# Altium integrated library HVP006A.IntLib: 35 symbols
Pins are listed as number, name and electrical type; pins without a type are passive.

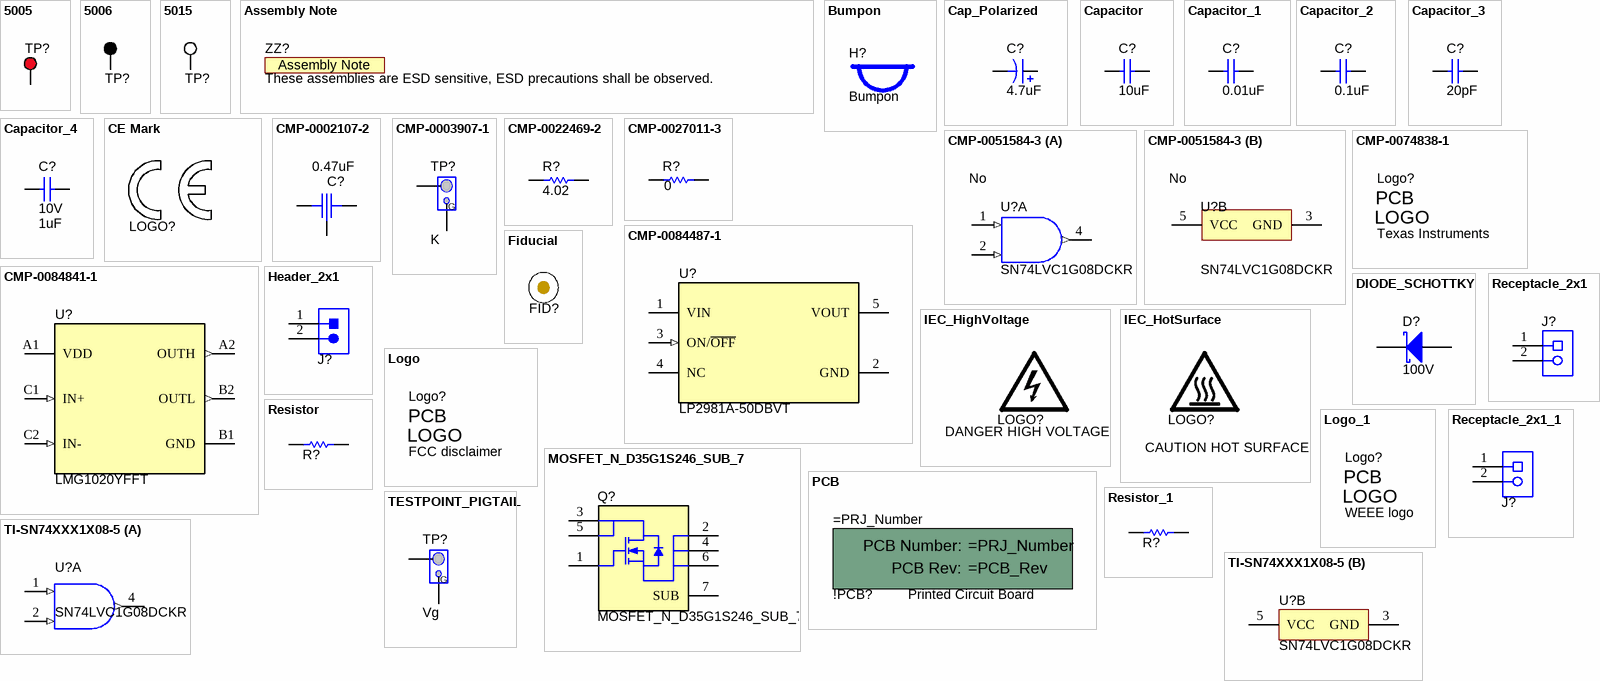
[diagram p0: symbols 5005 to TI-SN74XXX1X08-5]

## 5005
designator TP?  (value not drawn)
Test Point, Compact, Red, TH; Manufacturer: Keystone; CNHeader: FALSE; ContactFinish: Silver; CT: TRUE; Green_Lifecycle: Active; Green_REACh: Passed
footprint Keystone5005 (Keystone Compact loops)
pins: 1

## 5006
designator TP?  (value not drawn)
Test Point, Compact, Black, TH; Manufacturer: Keystone; CNHeader: FALSE; ContactFinish: Silver; CT: TRUE; Green_Lifecycle: Active; Green_REACh: Passed
footprint Keystone5006 (Keystone Compact loops)
pins: 1

## 5015
designator TP?  (value not drawn)
Test Point, Miniature, SMT; Manufacturer: Keystone; CNHeader: FALSE; CT: TRUE; Green_Lifecycle: Active; Green_REACh: Passed
footprint Testpoint_Keystone_Miniature (Miniature SMT test point)
pins: 1

## Assembly Note
designator ZZ?, comment These assemblies are ESD sensitive, ESD precautions shall be observed.  (no BOM)
CompType: AssemblyNote
footprint AssemblyNote (Assembly Note)

## Bumpon
designator H?
Bumpon, Hemisphere, 0.44 X 0.20, Clear; Manufacturer: 3M; PartNumber: SJ-5303 (CLEAR)
footprint Bumpon_SJ5003Transparent (3M Hemispherical Bumpon transparent)

## Cap_Polarized
designator C?  value 4.7uF  (hidden comment: Cap_Polarized)
CAP, AL, 4.7 uF, 100 V, +/- 20%, SMD; PartNumber: UUX2A4R7MCL1GS; Manufacturer: Nichicon; Polarized: Y; CompType: Capacitor; U/M: EA; Cap_F: 4.7µF; Value1: Unknown; VDC_V: 100V; IRMS_A: 42mA; TaMin_C: -55°C; TaMax_C: 105°C; Cap_Case: 8x6.2mm; SizeAreaWB_mm2: 106.09; SizeArea_mm2: 68.89; SizeX_mm: 8.3; SizeZ_mm: 6.5; AEC Category: Q200; AEC Qualified: N
footprint UUX_800x620 (SMD, 2-Leads, Dia 8mm)
pins: 1 +, 2 -

## Capacitor
designator C?  ValueDisplayed: 10uF  (hidden comment: Capacitor)
CAP, CERM, 10 uF, 25 V, +/- 10%, X7R, 1206; PartNumber: 885012208069; Manufacturer: Wurth Elektronik; Polarized: N; Value: 10uF; U/M: EA; Cap_F: 10µF; Value1: Unknown; VDC_V: 25V; TaMin_C: -55°C; TaMax_C: 125°C; Cap_Case: 1206; AEC Category: Q200; SizeArea_mm2: 5.12; SizeAreaWB_mm2: 10.92; SizeX_mm: 3.2; SizeY_mm: 1.6; SizeZ_mm: 1.35
footprint 1206 (1206 from SM-752 data)
footprint 1206L (1206 from SM-752 data)
footprint 1206M (1206 from SM-752 data)
pins: 1, 2

## Capacitor_1
designator C?, comment ValueDisplayed: 0.01uF  (hidden comment: Capacitor)
CAP, CERM, 0.01 uF, 100 V, +/- 1%, C0G/NP0, 0805; PartNumber: C0805C103F1GACTU; Manufacturer: Kemet; Polarized: N; Value: 0.01uF; U/M: EA; Cap_F: 10nF; Value1: Unknown; VDC_V: 100V; TaMin_C: -55°C; TaMax_C: 125°C; Cap_Case: 0805; SizeArea_mm2: 2.5; SizeAreaWB_mm2: 6.75; SizeX_mm: 2; SizeY_mm: 1.25; SizeZ_mm: 1.45; AEC Category: Q200
footprint 0805_HV (0805 with 30mil clearance between pads)
footprint 0805M (0805 from SM-752 data)
footprint 0805 (0805 from SM-752 data)
footprint 0805L (0805 from SM-752 data)
footprint 0805_HV1 (Custom footprint based on analyzing multiple manufacturer recommendations)
pins: 1, 2

## Capacitor_2
designator C?, comment ValueDisplayed: 0.1uF  (hidden comment: Capacitor)
CAP, CERM, 0.1 uF, 25 V, +/- 10%, X7R, 0603; PartNumber: GRM188R71E104KA01D; Manufacturer: MuRata; Polarized: N; Value: 0.1uF; U/M: EA; Cap_F: 100nF; Value1: Unknown; VDC_V: 25V; TaMin_C: -55°C; TaMax_C: 125°C; Cap_Case: 0603; AEC Category: Q200; SizeArea_mm2: 1.28; SizeAreaWB_mm2: 4.68; SizeX_mm: 1.6; SizeY_mm: 0.8; SizeZ_mm: 1
footprint 0603 (0603 from SM-752 data)
footprint 0603_HV (Ernesto recommended land pattern.  26 mil between pads.)
footprint 0603L (0603 from SM-752 data)
footprint 0603S
footprint 0603M (0603 from SM-752 data)
pins: 1, 2

## Capacitor_3
designator C?, comment ValueDisplayed: 20pF  (hidden comment: Capacitor)
CAP, CERM, 20 pF, 50 V, +/- 5%, C0G/NP0, 0402; PartNumber: GRM1555C1H200JA01D; Manufacturer: MuRata; Polarized: N; Value: 20pF; U/M: EA; Value1: Unknown; VDC_V: 50V; TaMin_C: -55°C; TaMax_C: 125°C; Cap_Case: 0402; SizeArea_mm2: 0.5; SizeAreaWB_mm2: 3; SizeX_mm: 1; SizeZ_mm: 0.6; AEC Category: Q200
footprint 0402 (0402 from SM-752 data)
footprint 0402S (Based on C0402S footprint from PADS legacy)
footprint 0402L (0402 from SM-752 data)
footprint 0402M (0402 from SM-752 data)
pins: 1, 2

## Capacitor_4
designator C?, comment VDC_V: 10V  ValueDisplayed: 1uF  (hidden comment: LWK107BJ105MV)
CAP, CERM, 1 uF, 10 V, +/- 20%, X5R, 0306; Manufacturer: Taiyo Yuden; TaMin_C: -55°C; Polarized: N; SizeAreaWB_mm2: 4.68; Value1: Unknown; U/M: EA; Value: 1uF; TaMax_C: 85°C; SizeZ_mm: 0.6; SizeX_mm: 0.8; SizeY_mm: 1.6; Cap_Case: 0306; SizeArea_mm2: 1.28; CompType: Capacitor; Cap_F: 1µF; AEC Category: Q200
footprint 0306 (based on TDK recommendation (similar to Taiyo Yuden and MuRata))
pins: 1, 2

## CE Mark
designator LOGO?  (value not drawn)  (no BOM)
SymbolCreator: a0412235
footprint CE_Mark_5mm (Minimum text height for CE Mark)
footprint CE_Mark_10mm (Double the minimum text height for CE Mark)

## CMP-0002107-2
designator C?, comment value 0.47uF  (hidden comment: Capacitor_Balanced)
Feedthru Capacitor, 0.47uF, 6.3V, SMD; PartNumber: YFF18PW0J474M; Manufacturer: TDK; CompType: Filter
footprint YFF18PW (TDK)
pins: 1, 2, 3

## CMP-0003907-1
designator TP?, comment K  (no BOM)
PIGTAIL; Manufacturer: Texas Instruments; Key: TESTPOINT_PIGTAIL; CompType: Test Point
footprint TESTPOINT_PIGTAIL (Pigtail)
pins: 1, 2

## CMP-0022469-2
designator R?, comment ValueDisplayed: 4.02  (hidden comment: CRCW06034R02FKEA)
RES, 4.02, 1%, 0.1 W, 0603; Manufacturer: Vishay-Dale; Power_W: 100mW; TempCo: 100 ppm/C; Value_Code: 4R02; U/M: EA; Value: 4.02; EIA_Code: E96; SizeX_mm: 1.6; SizeY_mm: 0.8; SizeZ_mm: 1; Value2: 0.1W; SizeArea_mm2: 1.28; CompType: Resistor; VDC_V: 75V; AEC Category: Q200
footprint 0603 (0603 from SM-752 data)
footprint 0603_HV (Ernesto recommended land pattern.  26 mil between pads.)
footprint 0603L (0603 from SM-752 data)
footprint 0603S
footprint 0603M (0603 from SM-752 data)
pins: 1, 2

## CMP-0027011-3
designator R?, comment ValueDisplayed: 0  (hidden comment: ERJ-1GE0R00C)
RES, 0, 5%, 0.05 W, 0201; Manufacturer: Panasonic; Power_W: 50mW; TempCo: 600 ppm/C; Value_Code: 0000; U/M: EA; Value: 0; EIA_Code: E24; SizeX_mm: 0.6; SizeY_mm: 0.3; SizeZ_mm: 0.26; Value2: 0.05W; SizeArea_mm2: 0.18; CompType: Resistor; VDC_V: 15V; AEC Category: Q200
footprint 0201 (Data from Kemet datasheet CC101_COM dated 7/28/11)
footprint 0201_Silk (Data from Kemet datasheet CC101_COM dated 7/28/11)
footprint 0201L (Data from Kemet datasheet CC101_COM dated 7/28/11)
footprint 0201M (Data from Kemet datasheet CC101_COM dated 7/28/11)
pins: 1, 2

## CMP-0051584-3
designator U?, comment 3-State Output: No  (hidden comment: SN74LVC1G08DCKR)
Single 2-Input Positive-AND Gate, DCK0005A, LARGE T&R; Manufacturer: Texas Instruments; tpd @ Nom Voltage(Max)(ns): 4.5,6,4,5; F @ Nom Voltage(Max)(Mhz): 150; ICC @ Nom Voltage(Max)(mA): 0.01; Bits(#): 1; VCC(Min)(V): 1.65; Gate Type: AND; Rating: Catalog; Output Type: CMOS; Voltage(Nom)(V): 1.8,2.5,3.3,5; Technology Family: LVC; VCC(Max)(V): 5.5; Input Type: CMOS/TTL; Output Drive (IOL/IOH)(Max)(mA): 32/-32; Logic: True; AEC Category: Q200; AEC Qualified: N; CompType: IC; SizeAreaWB_mm2: 9.3; SizeArea_mm2: 4.2; SizeX_mm: 2.1; SizeY_mm: 2.0; SizeZ_mm: 1.1
footprint DCK0005A_N (SOT353, 5-Leads, Body 2x1.3mm, Pitch 0.65mm, Lead Span 2.1mm, IPC Medium Density)
footprint DCK0005A_M (SOT353, 5-Leads, Body 2x1.3mm, Pitch 0.65mm, Lead Span 2.1mm, IPC Low Density)
footprint DCK0005A_L (SOT353, 5-Leads, Body 2x1.3mm, Pitch 0.65mm, Lead Span 2.1mm, IPC High Density)
part A pins: 1 A (in) "Input A", 2 B (in) "Input B", 4 Y (out) "Output Y"
part B pins: 3 GND (power) "Ground Pin", 5 VCC (power) "Power Pin"

## CMP-0074838-1
designator Logo?, comment Texas Instruments  (no BOM)
Texas Instrument Corporate Signature; SymbolCreator: a0412235; Library Reference: Logo; Lib Reference: TI_Logo
footprint TI_Horizontal_Overlay_Medium
footprint TI_Horizontal_Overlay_Small
footprint TI_Stacked_SolderMask_Small
footprint TI_Stacked_SolderMask_Small_Vertical
footprint TI_Symbol_Overlay_Medium
footprint TI_Symbol_Overlay_Small
footprint TI_Symbol_SolderMask_Medium
footprint TI_Symbol_SolderMask_Small
footprint TI_Horizontal_SolderMask_Medium
footprint TI_Horizontal_SolderMask_Small
footprint TI_Stacked_Overlay_Medium
footprint TI_Stacked_Overlay_Medium_Vertical
footprint TI_Stacked_Overlay_Small
footprint TI_Stacked_Overlay_Small_Vertical
footprint TI_Stacked_SolderMask_Medium
footprint TI_Stacked_SolderMask_Medium_Vertical

## CMP-0084487-1
designator U?, comment LP2981A-50DBVT
100-mA Ultra-Low Dropout Regulator With Shutdown, 0.75% Tolerance, DBV0005A (SOT-23-5); Manufacturer: Texas Instruments; Alternate PartNumber: LP2981A-50DBVR; SizeY_mm: 2.9; SizeZ_mm: 1.45; SizeAreaWB_mm2: 14.82; CompType: IC; AEC Qualified: N; Rating: Catalog; SizeX_mm: 2.8; AEC Category: Q200; SizeArea_mm2: 8.12
footprint DBV0005A_N (SOT23, 5-Leads, Body 2.9x1.6mm, Pitch 0.95mm, Lead Span 2.8mm, IPC Medium Density)
footprint DBV0005A_M (SOT23, 5-Leads, Body 2.9x1.6mm, Pitch 0.95mm, Lead Span 2.8mm, IPC Low Density)
footprint DBV0005A_L (SOT23, 5-Leads, Body 2.9x1.6mm, Pitch 0.95mm, Lead Span 2.8mm, IPC High Density)
pins: 1 VIN (power), 2 GND (power), 3 ON/~{OFF} (in), 4 NC, 5 VOUT (power)

## CMP-0084841-1
designator U?, comment LMG1020YFFT
5V, 7A/5A Low Side GaN Driver With 60MHz/1ns Speed, YFF0006AEAE (DSBGA-6); Manufacturer: Texas Instruments; Alternate PartNumber: LMG1020YFFR; SizeAreaWB_mm2: 4.190848; SizeX_mm: 0.856; SizeZ_mm: 0.625; CompType: IC; SizeY_mm: 1.258; SizeArea_mm2: 1.076848; AEC Qualified: N; Rating: Catalog; AEC Category: Q200
footprint YFF0006AEAE (DSBGA-6)
pins: A1 VDD (power), A2 OUTH (out), B1 GND (power), B2 OUTL (out), C1 IN+ (in), C2 IN- (in)

## DIODE_SCHOTTKY
designator D?  value 100V  (hidden comment: DIODE_SCHOTTKY)
Diode, Schottky, 100 V, 2 A, PowerDI123; PartNumber: DFLS2100-7; Manufacturer: Diodes Inc.; U/M: EA; Vf_V: 8.6dV; Value1: 2A; Value2: 0.86V; TJmax_C: 175°C; SizeAreaWB_mm2: 13.066; SizeArea_mm2: 6.586; SizeX_mm: 3.7; SizeY_mm: 1.78; SizeZ_mm: 0.98; AEC Category: Q101; Green_Lifecycle: Not Set; Green_REACh: Incomplete
footprint PowerDI123 (Diodes Inc recommended land pattern, document number DS30628 Rev. 6-2)
pins: 1 K, 2 A

## Fiducial
designator FID?  (value not drawn)
Fiducial mark.  There is nothing to buy or mount.
footprint Fiducial10-30
footprint Fiducial15-30
footprint Fiducial10-20
footprint Fiducial20-40
footprint Fiducial6.4-20

## Header_2x1
designator J?  (value not drawn)
Header, 100mil, 2x1, Gold, TH; PartNumber: HTSW-102-07-G-S; Manufacturer: Samtec; CNHeader: True; CT: False; Green_Lifecycle: Active; Green_REACh: Passed
footprint Samtec_HTSW-102-07-G-S (Samtec 100mil, 1x2, 230 mil above insulator)
pins: 1, 2
1 alternate drawing of the same symbol

## IEC_HighVoltage
designator LOGO?, comment DANGER HIGH VOLTAGE  (no BOM)
IEC 61010-1 High Voltage Warning; SymbolCreator: a0412235; Lib Reference: IEC_HighVoltage
footprint IEC_HighVoltage_Large
footprint IEC_HighVoltage_Small
footprint IEC_HighVoltage_Medium

## IEC_HotSurface
designator LOGO?, comment CAUTION HOT SURFACE  (no BOM)
IEC 61010-1 Hot Surface Warning; SymbolCreator: a0412235; Lib Reference: IEC_HotSurface
footprint IEC_HotSurface_Large
footprint IEC_HotSurface_Small
footprint IEC_HotSurface_Medium

## Logo
designator Logo?, comment FCC disclaimer  (no BOM)
FCC_disclaimer; Library Reference: Logo
footprint FCC_disclaimer
footprint FCC_disclaimer_stacked

## Logo_1
designator Logo?, comment WEEE logo  (no BOM)
footprint WEEE_Minimum (WEEElie bin)

## MOSFET_N_D35G1S246_SUB_7
designator Q?
MOSFET, N-CH, 200 V, 8.5 A, 2.766x0.68mm; PartNumber: EPC2019; Manufacturer: EPC; Alternate Manufacturer: None; U/M: EA; ChType: N; Value: 200V; Value2: 1.8 nC; QgTyp_nC: 1.8; Vgs_V: 6V; IdsMax_A: 8.5A; SizeAreaWB_mm2: 7.3437; SizeArea_mm2: 2.6277; SizeX_mm: 2.766; SizeY_mm: 0.95; SizeZ_mm: 0.815; AEC Category: Q101
footprint EPC2019 (SMD. 7-Leads, Body 2.766x0.95mm)
pins: 1 G, 2 S, 3 D, 4 S, 5 D, 6 S, 7 SUB

## PCB
designator !PCB?, comment Printed Circuit Board  (mechanical)
Manufacturer: Any; CompType: PCB
1 alternate drawing of the same symbol

## Receptacle_2x1
designator J?  (value not drawn)
Terminal Block, 2x1, 5.08mm, TH; PartNumber: 282841-2; Manufacturer: TE Connectivity; CNHeader: FALSE; CT: TRUE; Green_Lifecycle: Active; Green_REACh: Passed
footprint TEC_282841-2 (TE Connectivity)
pins: 1, 2

## Receptacle_2x1_1
designator J?, comment Receptacle_2x1  (value not drawn)
Terminal Block, 2.54mm, 2x1, Brass, TH; PartNumber: OSTVN02A150; Manufacturer: On-Shore Technology; CNHeader: False; CT: True; Green_Lifecycle: Not Set; Green_REACh: Incomplete
footprint On-Shore_OSTVN02A150 (Terminal Block, 2.54mm, 2-pole, Brass, TH)
pins: 1, 2

## Resistor
designator R?  (value not drawn)
RES, 10, 5%, 0.063 W, AEC-Q200 Grade 0, 0402; PartNumber: CRCW040210R0JNED; Manufacturer: Vishay-Dale; Value: 10; Value_Code: 10R0; Power_W: 63mW; Value2: 0.063W; VDC_V: 50V; TempCo: 200 ppm/C; SizeArea_mm2: 0.5; SizeX_mm: 1; SizeZ_mm: 0.6; EIA_Code: E24; AEC Category: Q200; AEC Qualified: Y; AEC Grade: 0
footprint 0402 (0402 from SM-752 data)
footprint 0402S (Based on C0402S footprint from PADS legacy)
footprint 0402L (0402 from SM-752 data)
footprint 0402M (0402 from SM-752 data)
pins: 1, 2

## Resistor_1
designator R?, comment Resistor  (value not drawn)
RES, 50, 1%, 0.1 W, AEC-Q200 Grade 0, 0603; PartNumber: CRCW060350R0FKEA; Manufacturer: Vishay-Dale; Value: 50; Value_Code: 50R0; Power_W: 100mW; Value2: 0.1W; VDC_V: 75V; TempCo: 100 ppm/C; SizeArea_mm2: 1.28; SizeX_mm: 1.6; SizeY_mm: 0.8; SizeZ_mm: 1; AEC Category: Q200; AEC Qualified: Y; AEC Grade: 0
footprint 0603 (0603 from SM-752 data)
footprint 0603_HV (Ernesto recommended land pattern.  26 mil between pads.)
footprint 0603L (0603 from SM-752 data)
footprint 0603S
footprint 0603M (0603 from SM-752 data)
pins: 1, 2

## TESTPOINT_PIGTAIL
designator TP?, comment Vg  (no BOM)
PIGTAIL; Manufacturer: Texas Instruments; Key: TESTPOINT_PIGTAIL; CompType: Test Point
footprint TESTPOINT_PIGTAIL (Pigtail)
pins: 1, 2

## TI-SN74XXX1X08-5
designator U?, comment SN74LVC1G08DCKR
Single 2-Input Positive-AND Gate, DCK0005A, LARGE T&R; Manufacturer: Texas Instruments; tpd @ Nom Voltage(Max)(ns): 4.5,6,4,5; F @ Nom Voltage(Max)(Mhz): 150; ICC @ Nom Voltage(Max)(mA): 0.01; Bits(#): 1; VCC(Min)(V): 1.65; Gate Type: AND; Rating: Catalog; Output Type: CMOS; Voltage(Nom)(V): 1.8,2.5,3.3,5; Technology Family: LVC; VCC(Max)(V): 5.5; Input Type: CMOS/TTL; Schmitt Trigger: No; Output Drive (IOL/IOH)(Max)(mA): 32/-32; Logic: True; AEC Category: Q200; AEC Qualified: N; CompType: IC; SizeAreaWB_mm2: 9.3; SizeArea_mm2: 4.2; SizeX_mm: 2.1; SizeY_mm: 2.0; SizeZ_mm: 1.1
footprint DCK0005A_N (SOT353, 5-Leads, Body 2x1.3mm, Pitch 0.65mm, Lead Span 2.1mm, IPC Medium Density)
footprint DCK0005A_M (SOT353, 5-Leads, Body 2x1.3mm, Pitch 0.65mm, Lead Span 2.1mm, IPC Low Density)
footprint DCK0005A_L (SOT353, 5-Leads, Body 2x1.3mm, Pitch 0.65mm, Lead Span 2.1mm, IPC High Density)
part A pins: 1 A (in) "Input A", 2 B (in) "Input B", 4 Y (out) "Output Y"
part B pins: 3 GND (power) "Ground Pin", 5 VCC (power) "Power Pin"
